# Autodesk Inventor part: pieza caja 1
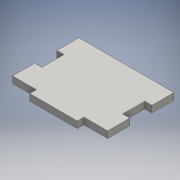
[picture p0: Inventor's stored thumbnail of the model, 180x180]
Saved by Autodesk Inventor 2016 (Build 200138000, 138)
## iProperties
Created: 2016-06
Part Number: pieza caja 1
Material: Genérico
Document SubType Name: Modeling
Designer: adm
Density: 1 g/cm^3
Appearance: Valor por defecto
Author: adm
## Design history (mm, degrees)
sketch "Boceto1"
  geometry: L1 (-10.75, -15.262)-(10.75, -15.262); L2 (21.5, -12.262)-(21.5, -2.262); L3 (21.5, 17.738)-(-21.5, 17.738); L4 (-21.5, -17.738)-(21.5, 17.738); L5 (21.5, -17.738)-(-21.5, 17.738); L6 (10.75, -12.262)-(10.75, -15.262); L7 (-10.75, -12.262)-(-10.75, -15.262); L8 (21.5, -12.262)-(10.75, -12.262); L9 (-10.75, -12.262)-(-21.5, -12.262); L10 (18.106, 3.113)-(18.275, 3.113); L11 (-21.5, -2.262)-(-18.275, -2.262); L12 (-21.5, 7.738)-(-18.275, 7.738); L13 (18.106, 7.738)-(21.5, 7.738); L14 (18.106, -2.262)-(21.5, -2.262); L15 (-18.275, 7.738)-(-18.275, -2.262); L16 (18.275, 7.738)-(18.275, -2.262); L17 (-21.5, 17.738)-(-21.5, 7.738); L18 (-21.5, -2.262)-(-21.5, -12.262); L19 (21.5, 17.738)-(21.5, 7.738); 1 further point
  constraints: 38 end point, 6 parallel, 3 point on line, 2 horizontal, 2 midpoint, 2 vertical, 1 perpendicular
  dimensions: "d13" = 43 distance of L3.start L3.end; "d14" = 30 distance between parallel lines of L9 L3; "d15" = 30 distance between parallel lines of L8 L3; "d16" = 3 distance between parallel lines of L1 L8; "d17" = 10 distance of L3.start L13.end; "d18" = 10 distance of L3.end L12.start; "d19" = 10 distance of L11.start L9.end; "d20" = 10 distance of L2.start L2.end
extrude "Extrusión1" new body sketch "Boceto1" distance "d11" = 3; taper "d12" = 0 deg
node "Sólido1"
other parameters: "d10" = 3
